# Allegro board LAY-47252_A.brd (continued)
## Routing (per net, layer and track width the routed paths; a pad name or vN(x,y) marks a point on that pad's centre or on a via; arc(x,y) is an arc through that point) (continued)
N16747780: length 1.1
  TOP w0.508: D35.A 11.09,7.87 C10.3
N16752305: length 3
  BOTTOM w0.152: R4.2 54.31,12.97 C26.1 54.33,12.97 R3.2
N16762980: length 3
  BOTTOM w0.152: R24.2 54.33,2.75 C12.1 54.31,2.75 R23.2
N16766876: length 1
  TOP w0.381: C32.3 39.55,7.94 D29.A
N16781617: length 2.3
  TOP w0.152: LED1.3 23.48,20.62 23.13,20.62 22.97,20.47 R20.2
N16781620: length 1.3
  TOP w0.152: R19.2 23.49,19.09 LED1.2
N16805422: length 1
  TOP w0.508: C8.3 11.14,5.21 D16.A
N16833767: length 1
  TOP w0.508: C28.3 11.16,3.33 D1.A
N16834186: length 1.2
  BOTTOM w0.381: D34.A 39.09,6.2 C3.3
N16850472: length 2.7
  TOP w0.203: IC3.12 17.98,5.17 17.78,5.37
  TOP w0.254: 17.78,5.37 17.31,5.84 C17.2 L1.2
N16850531: length 2.1
  TOP w0.152: IC3.18 15.16,2.92 C30.1 L3.1
N16850565: length 2.3
  TOP w0.152: L2.2 15.27,5.14 15.5,5.14 16.18,4.46 IC3.15
N16850567: length 1.9
  TOP w0.152: L2.1 13.89,5.47 L3.2
N16850641: length 1.5
  TOP w0.152: IC3.19 15.55,2.52 14.91,1.88 L4.2
N16885160: length 4.2
  TOP w0.152: IC3.13 17.58,5 17.14,5.44 16.19,5.44 16.18,5.45 16.08,5.45 15.72,5.8 15.72,5.82 15.3,6.24 15.3,6.51 R27.2
N16895535: length 1.7
  BOTTOM w0.508: D8.A 50.45,9.24 F1.1
N16899617: length 1.7
  BOTTOM w0.508: F2.1 50.45,19.46 D6.A
N16901866: length 12.8
  TOP w0.381: D26.C 12.48,13.38 12.48,15.52 12.86,15.9 13.25,15.9 13.58,16.23 P13.1
  BOTTOM w0.381: 16.06,17.68 F3.1 ; F3.1 16.83,18.69 ; F3.1 15.28,18.69 ; F3.1 16.06,19.71 ; P13.1 14.73,17.37 ; P13.1 12.42,17.37 ; P13.1 13.58,18.53
N16903080: length 4.4
  TOP w0.381: P12.1 7.23,12.56 R28.2 8.2,12.55 8.29,12.64 D25.C
N16904839: length 6.9
  TOP w0.381: P11.2 12.19,17.37 ; P11.2 11.04,18.53 ; P11.2 9.88,17.37 ; 6.07,17.37 P12.2 ; P12.2 7.23,18.53 ; P12.2 8.38,17.37
N16939568: length 2.3
  TOP w0.254: C68.1 47.59,13.79 46.51,14.87 IC7.6

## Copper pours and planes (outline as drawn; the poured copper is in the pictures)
3V3 on TOP: 32.2,18.54 32.2,16.64 33.43,16.64 33.43,18.54
3V3 on L3_PWR: 62.34,21.56 62.34,0.38 0.53,0.38 0.53,21.56
5V on TOP: 42,21.67 42,17.48 44.41,17.48 44.67,17.22 44.67,16.84 49.24,16.84 49.49,17.09 49.49,19 49.87,19.38 53.3,19.38 53.3,21.67
5V on BOTTOM: 24.22,18.31 31.38,18.31 32.5,17.2 39.03,17.2 40.58,18.75 46.95,18.75 47.08,18.87 47.08,20.4 47.71,21.03 52.03,21.03 52.54,20.52 53.43,20.52 53.43,21.67 17.36,21.67 17.36,17.3 18,16.66 22.57,16.66
5V on L3_PWR: 16.73,20.52 16.73,9.12 15.84,8.23 13.02,8.23 12.92,8.33 12.92,10.79 11.7,10.79 11.7,2.59 23.84,2.59 25.08,3.84 40.7,3.84 41.67,2.87 49.67,2.87 50.58,1.96 54.67,1.96 55.31,1.32 55.79,1.32 55.79,2.74 55.31,3.23 51.88,3.23 48.86,6.25 48.86,7.06 51.52,9.73 55.59,9.73 56.1,10.24 56.1,11.89 55.46,12.52 50.25,12.52 45.4,7.67 24.6,7.67 23.23,6.3 18.12,6.3 18.12,7.57 19.14,8.59 19.14,20.52
GND on TOP: 41.62,16.71 41.62,13.16 52.41,13.16 52.41,16.84 41.74,16.84
GND on TOP: 30.5,18.54 30.5,16.63 31.71,16.63 31.71,18.54
GND on TOP: 39.08,0.42 51.58,0.42 51.58,5.65 48.49,5.65 48.49,1.4 40.25,1.4 40.25,2.69 39.08,2.69
GND on TOP, BOTTOM: 60.08,12.1 62.47,12.1 62.47,10.17 62.47,10.17 62.47,5.58 62.47,5.58 62.47,3.56 59.85,3.56 59.85,5.58 61.48,5.58 61.48,10.17 60.08,10.17
GND on TOP, BOTTOM: 60.08,21.04 62.47,21.04 62.47,19.11 62.47,19.11 62.47,14.53 62.47,14.53 62.47,12.51 59.85,12.51 59.85,14.53 61.48,14.53 61.48,19.11 60.08,19.11
GND on BOTTOM: 41.62,18.36 41.62,15.7 49.24,15.7 49.36,15.57 50.63,15.57 50.63,16.08 49.75,16.97 49.75,20.4 49.36,20.78 47.71,20.78 47.46,20.52 47.46,18.62 47.21,18.36
GND on BOTTOM: 35.01,12.4 35.01,5.92 35.27,5.66 37.05,5.66 38.32,6.93 38.32,11.13 37.05,12.4
GND on BOTTOM: 27.48,7.7 27.56,7.61 31.9,7.61 31.9,8.39 31.83,8.46 29.12,8.46 28.74,8.84 28.74,9.7 29.25,10.21 29.25,13.94 30.19,14.88 31.36,14.88 31.86,15.39 31.86,17.14 31.28,17.73 24.42,17.73 24.19,17.5 24.19,16.15 25.16,15.19 25.16,14.63 25.36,14.43 26.53,14.43 27.48,13.48
GND on L2_GND: 62.34,21.56 62.34,0.38 0.53,0.38 0.53,21.56
GND on L3_PWR: 51.9,5.28 51.9,6.68 53.56,8.33 56.73,8.33 58.51,10.11 58.51,15.19 58.38,15.32 52.16,15.32 51.78,15.7 51.78,17.86 62.32,17.86 62.32,5.03 60.16,5.03 58.76,6.43 57.62,6.43 56.48,5.28
(no net) on BOTTOM: 57.11,18.41 58.81,18.41 58.81,19.58 58.68,19.71 55.98,19.71 55.69,19.42 54.17,19.42 53.2,18.45 52.23,18.45 52.23,17.23 53.23,17.23 54.17,18.17 56.48,18.17 56.48,18.18 56.88,18.18
(no net) on BOTTOM: 53.38,19.14 53.38,19.57 51.93,19.57 51.93,19.9 51.09,19.9 51.09,19.14
(no net) on BOTTOM: 57.14,9.45 58.81,9.45 58.81,10.52 56.25,10.52 55.82,10.08 55.82,9.32 55.69,9.19 54.17,9.19 53.2,8.23 52.23,8.23 52.23,7.01 53.23,7.01 54.17,7.95 56.48,7.95 57.01,8.48 57.01,9.32
(no net) on BOTTOM: 53.38,8.92 53.38,9.35 51.93,9.35 51.93,9.68 51.09,9.68 51.09,8.92
Net_2 on BOTTOM (solid shape): 46.82,5.11 46.41,5.11 46.41,5.87 45.76,5.11 45.33,5.76 45.76,6.41 45.76,5.65 46.4,6.41 46.82,6.41
Net_3 on BOTTOM (solid shape): 44.9,6.01 45.16,6.41 45.65,6.41 45.22,5.76 45.65,5.11 45.16,5.11 44.9,5.52 44.65,5.11 44.16,5.11 44.59,5.76 44.16,6.41 44.65,6.41
Net_4 on BOTTOM (solid shape): 44.39,5.9 44.48,5.76 44.05,5.11 44.05,5.39 43.4,5.39 43.37,5.39 43.31,5.4 43.26,5.41 43.21,5.44 43.17,5.47 43.13,5.5 43.09,5.54 43.06,5.59 43.04,5.64 43.02,5.69 43.02,5.74 43.01,5.98 43.43,5.98 43.43,5.8 43.44,5.78 43.46,5.75 43.48,5.73 43.51,5.72 43.52,5.72 44.05,5.72 44.05,6.07 43.52,6.07 43.51,6.07 43.48,6.06 43.46,6.05 43.44,6.02 43.43,5.99 43.43,5.98 43.01,5.98 43.02,6.05 43.02,6.11 43.04,6.16 43.06,6.21 43.09,6.25 43.13,6.3 43.17,6.33 43.21,6.36 43.26,6.38 43.31,6.4 43.37,6.41 43.4,6.41 44.05,6.41
N02898 on BOTTOM (solid shape): 58.81,19.58 58.81,18.41 57.11,18.41 56.88,18.18 56.48,18.18 56.48,18.17 54.17,18.17 53.23,17.23 52.23,17.23 52.23,18.45 53.2,18.45 54.17,19.42 55.69,19.42 55.98,19.71 58.68,19.71
N03706 on BOTTOM (solid shape): 58.81,9.45 57.14,9.45 57.01,9.32 57.01,8.48 56.48,7.95 54.17,7.95 53.23,7.01 52.23,7.01 52.23,8.23 53.2,8.23 54.17,9.19 55.69,9.19 55.82,9.32 55.82,10.08 56.25,10.52 58.81,10.52
N16948 on TOP: 5.93,2.74 5.93,1.09 9.74,1.09 9.74,3.51 7.96,3.51 7.45,3 6.18,3
N18118 on BOTTOM: 38.3,3.95 38.3,3.15 39.21,2.24 42.82,2.24 42.82,2.87 41.03,2.87 39.96,3.95
N20024 on BOTTOM: 42.89,15.44 42.89,14.05 43.68,13.26 43.68,9.12 47.71,9.12 47.71,13.54 49.11,13.54 49.24,13.67 49.24,15.19 48.98,15.44
N16895554 on BOTTOM (solid shape): 51.93,9.35 53.38,9.35 53.38,8.92 51.09,8.92 51.09,9.68 51.93,9.68
N16899266 on BOTTOM (solid shape): 51.93,19.57 53.38,19.57 53.38,19.14 51.09,19.14 51.09,19.9 51.93,19.9
N16901866 on BOTTOM: 12.15,17.09 16.85,17.09 17.11,17.35 17.11,20.65 12.15,20.65
N16904839 on TOP: 5.3,18.75 5.3,16.08 12.41,16.08 12.41,18.75

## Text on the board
BOTTOM: 170-47252 REV A | 07 | L4_SS
Board Geometry/Soldermask Bottom: 08 | SECONDARY SOLDERMASK
Ref Des/Silkscreen Bottom: UCANS32K146-01 | 09 | SECONDARY SILKSCREEN
User.Comments: 1 OF 1 | TEST PROBE | 1/1 | 1
TOP: 04 | L1_PS
Board Geometry/Soldermask Top: 03 | PRIMARY SOLDERMASK
Ref Des/Silkscreen Top: S | G | 02 | PRIMARY SILKSCREEN | +
L2_GND: 05 | L2_GND
L3_PWR: 06 | L3_PWR
XSECTION_CHART: *  SURFACE - AIR 0 MIL | *  DIELECTRIC - SOLDERMASK 0.4 MIL | L1 TOP CONDUCTOR - COPPER 0.67 MIL | *  DIELECTRIC - FR-4 2.44 MIL | L2 L2_GND PLANE - COPPER 2.44 MIL | *  DIELECTRIC - FR-4 46.85 MIL | L3 L3_PWR PLANE - COPPER 2.44 MIL | L4 BOTTOM CONDUCTOR - COPPER 0.67 MIL | DESIGN CROSS SECTION CHART | ___________________________ | TOTAL THICKNESS 58.75 MIL | 1-4
DIMENSION: SCALE: NONE | BOARD THICKNESS TOLERANCE +/-10% | 8 | 19 | 16 | DETAIL | LAYER STACKUP | PRIMARY DATUM | GRID ORIGIN | A
PASTEMASK_TOP: 01 | PASTEMASK TOP
User.5: 10 | SECONDARY PASTEMASK
User.22: OF 10
User.25: 22. THIS FAB_VIAFILL.ART SHOWS LOCATIONS OF VIA-IN-PAD TO BE FILLED. | 1/1 | 2
User.26: 24. | 1/1 | 3 | CAD DESIGNER: DELETE THIS FAB PAGE IF BACKDRILL IS NOT USED ON THIS DESIGN. | FAB SUPPLIER: DISREGARD THIS PAGE IF BACKDRILL REQUIRMENT IS NOT PROVIDED.
User.30: 5.00 | 11.50 | 120
User.31: TOP TO LAYER X | BACK DRILL REFERENCE | BOTTOM TO LAYER X | LAYER X | MUST CUT LAYER | LAYER X+1 | MUST NOT CUT LAYER | LAYER X-1
User.32: FIGURE | FINISHED_SIZE | 10.0 | 36.0 | 39.0 | 40.0 | 45.0 | DRILL CHART: TOP to BOTTOM | ALL UNITS ARE IN MILS | TOLERANCE_DRILL | +0.0/-10.0 | +3.0/-3.0 | +4.0/-4.0 | PLATED | QTY | 226 | 8 | 1 | 10 | 13
